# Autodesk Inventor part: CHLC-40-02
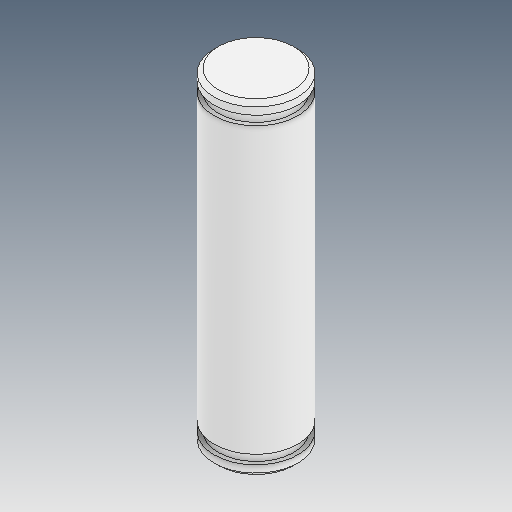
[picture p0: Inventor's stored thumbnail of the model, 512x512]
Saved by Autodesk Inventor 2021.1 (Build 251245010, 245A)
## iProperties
Created: 2021-05
Part Number: CHLC-40-02
Material: Ogólny
Document SubType Name: Modeling
Designer: user
Density: 1 g/cm^3
Appearance: Domyślna
Author: user
Revision Number: ÈÎºÎ
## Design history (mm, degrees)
feature "ÊäÈë1"
node "Bryła1"
